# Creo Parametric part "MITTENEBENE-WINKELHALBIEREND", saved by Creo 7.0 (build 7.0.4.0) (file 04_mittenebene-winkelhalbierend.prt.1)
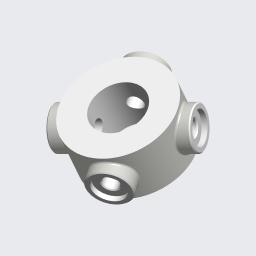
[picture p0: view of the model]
Units: millimeter Kilogram Sec (mmKs); MM, KILOGRAM, SECS
Materials in the file: S235JRG2

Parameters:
  PTC_MATERIAL_NAME = "S235JRG2"
  BENENNUNG = "XXX"
  DATUM = "XX.XX.XX"
  ERSTELLER = "ARINDA"
  TEILETYP = "Fertigungsteil"
  SELECT_EN_NAME = "S235JRG2"
  SELECT_DIN_NAME = "RSt37-2"
  SELECT_DIN_NUMBER = "1.0038"
  SELECT_ASTM_NAME = "A 283 M Grade 2"
  MATERIAL_GROUP = "ME_ST_Baustahl"
  STANDARD_EN_DELIVERYSPEC = "DIN EN 10025"
  STANDARD_DIN_DELIVERYSPEC = "DIN 17100"

Other parameters: MASSE

Created from: ARINDA-STARTTEIL.PRT

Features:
  1. coordinate system "CS0"
  2. datum plane "DTM1", "T_RECHTS_Y-Z"
  3. datum plane "DTM2", "T_OBEN_X-Z"
  4. datum plane "DTM3", "T_VORNE_X-Y"
  5. datum axis "T_X-ACHSE"
  6. datum axis "A_1"
  7. datum axis "A_2"
  8. extrusion "Profil 1"
  9. pattern "Muster 1"
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
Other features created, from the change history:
  extrusion "Profil 2"
  hole "Bohrung 1"
  round "Rundung 1"
  chamfer "Fase 1"
  pattern "Muster 1"
  extrusion "Profil 2 [2]"
  extrusion "Profil 2 [3]"
  extrusion "Profil 2 [4]"
  pattern "Muster 2"
  hole "Bohrung 1 [2]"
  hole "Bohrung 1 [3]"
  hole "Bohrung 1 [4]"
  group "LOCAL_GROUP"
  group "LOCAL_GROUP_1"
  extrusion "Profil 3"
  hole "Bohrung 2"
  round "Rundung 2"
  chamfer "Fase 2"
  group "LOCAL_GROUP_2"
  extrusion "Profil 4"
  hole "Bohrung 3"
  round "Rundung 3"
  chamfer "Fase 3"
  group "LOCAL_GROUP_3"
  extrusion "Profil 5"
  hole "Bohrung 4"
  round "Rundung 4"
  chamfer "Fase 4"
  hole "Bohrung 5"

Other named items: T_BASIC, T_Y-ACHSE, T_Z-ACHSE

Layers: 00_STD-ACHSEN, 00_STD-EBENEN, 00_STD-KOORDSYS, VOLUMENGEOMETRIE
